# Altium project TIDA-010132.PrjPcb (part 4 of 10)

## Sheet AFE1-RX-TX-INTERFACE.SchDoc
size 431 x 279 mm; Date: Not shown in title block; ApprovedBy: Not shown in title block; CheckedBy: Not shown in title block; Author: Not shown in title block; CompanyName: Not shown in title block; DrawnBy: Avinash N; Engineer: Not shown in title block; Organization: Not shown in title block; Address1: Not shown in title block; Address2: Not shown in title block; Address3: Not shown in title block; Address4: Not shown in title block; DocumentNumber: 1; Revision: Use project parameter SCH_Rev; SheetNumber: 8; SheetTotal: 32; PageSetup: Record=PageOptions¦CenterHorizontal=True¦CenterVertical=True¦PrintScale=1.00¦XCorrection=1.00¦YCorrection=1.00¦PrintKind=0¦BorderSize=5000000¦LeftOffset=0¦BottomOffset=0¦Orientation=2¦PaperLength=1000¦PaperWidth=1000¦Scale=100¦PaperSource=15¦PrintQuality=600¦MediaType=1¦DitherType=10¦PaperKind=Letter¦PrintScaleMode=1
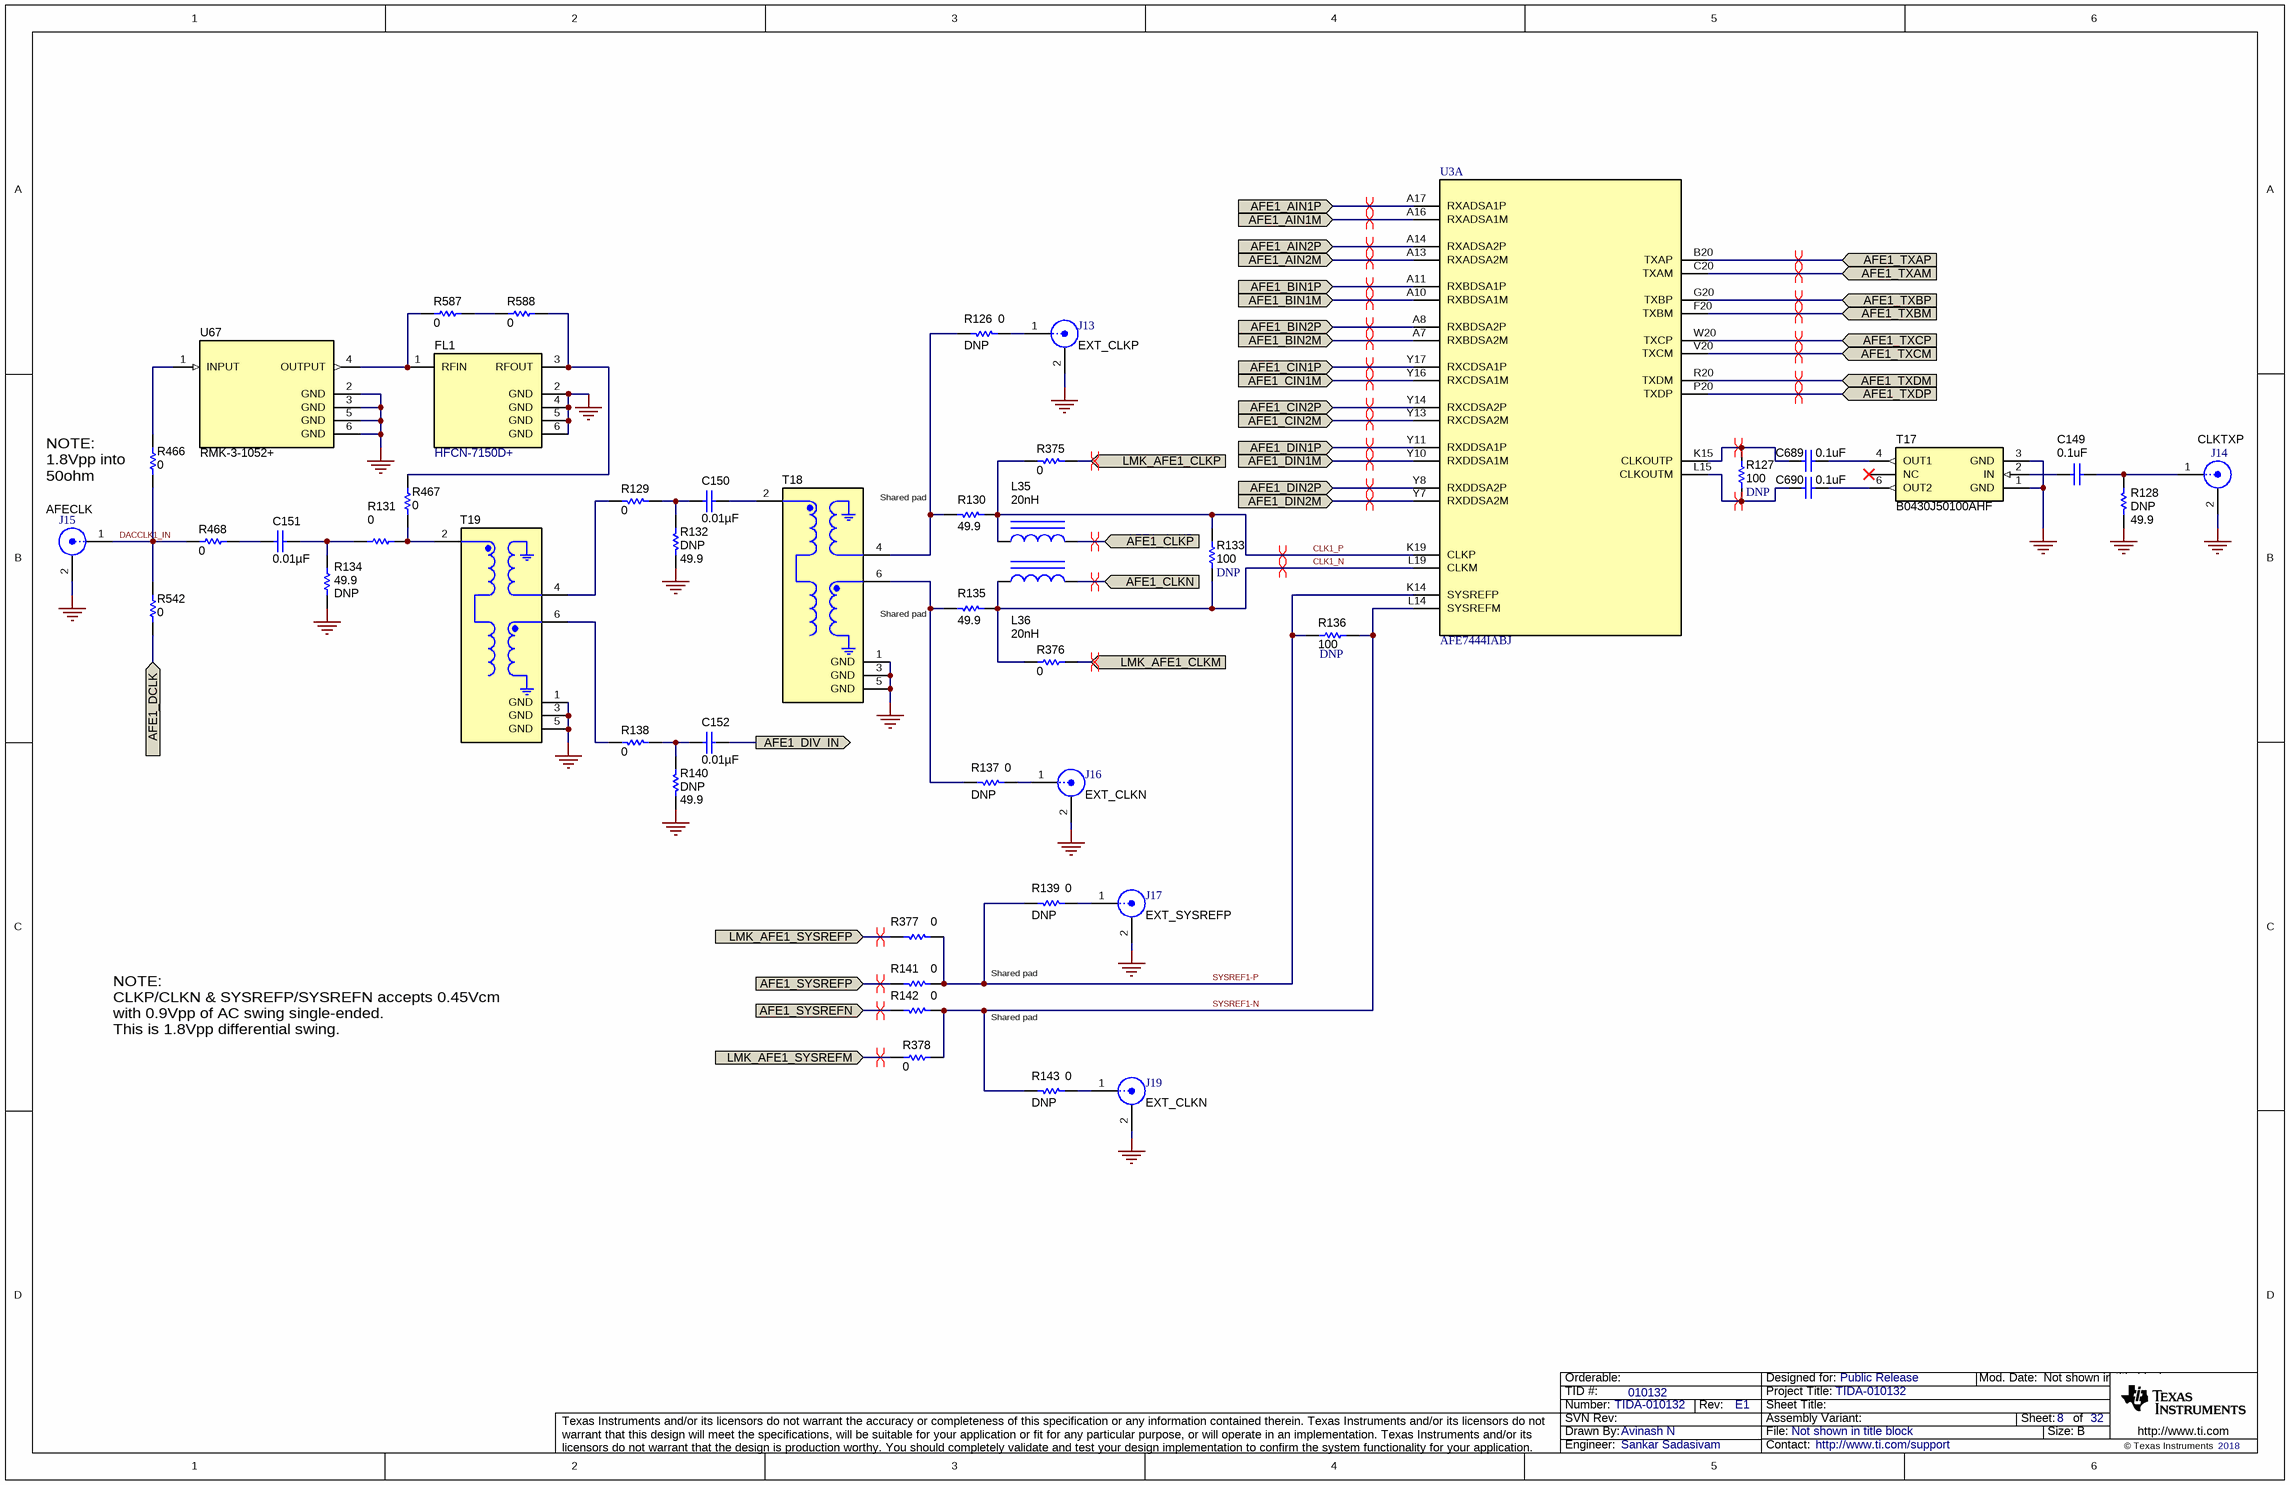
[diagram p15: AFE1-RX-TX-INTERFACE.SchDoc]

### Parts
C149  ValueDisplayed: 0.1uF  [0402_065]  (hidden comment: 550L104KCAT)
C150  ValueDisplayed: 0.01µF  [0402]  (hidden comment: GRM155R71H103KA88D)
C151  ValueDisplayed: 0.01µF  [0402]  (hidden comment: GRM155R71H103KA88D)
C152  ValueDisplayed: 0.01µF  [0402]  (hidden comment: GRM155R71H103KA88D)
C689  ValueDisplayed: 0.1uF  [0402_065]  (hidden comment: 550L104KCAT)
C690  ValueDisplayed: 0.1uF  [0402_065]  (hidden comment: 550L104KCAT)
FL1  HFCN-7150D+  [FV1206-1]
J13  EXT_CLKP  [Molex_0853050232]
J14  CLKTXP  [Molex_0853050232]
J15  AFECLK  [Molex_0853050232]
J16  EXT_CLKN  [Molex_0853050232]
J17  EXT_SYSREFP  [Molex_0853050232]
J19  EXT_CLKN  [Molex_0853050232]
L35  ValueDisplayed: 20nH  [LQG15WZ_02]  (hidden comment: LQG15WZ20NH02D)
L36  ValueDisplayed: 20nH  [LQG15WZ_02]  (hidden comment: LQG15WZ20NH02D)
R126  DNP  ValueDisplayed: 0  [0402]
R127  ValueDisplayed: 100  [0201]  (hidden comment: ERJ-1GEF1000C)
R128  DNP  ValueDisplayed: 49.9  [0402]
R129  ValueDisplayed: 0  [0402]  (hidden comment: ERJ-2GE0R00X)
R130  ValueDisplayed: 49.9  [0402]  (hidden comment: ERJ-2RKF49R9X)
R131  ValueDisplayed: 0  [0402]  (hidden comment: ERJ-2GE0R00X)
R132  DNP  ValueDisplayed: 49.9  [0402]
R133  ValueDisplayed: 100  [0201]  (hidden comment: ERJ-1GEF1000C)
R134  DNP  ValueDisplayed: 49.9  [0402]
R135  ValueDisplayed: 49.9  [0402]  (hidden comment: ERJ-2RKF49R9X)
R136  ValueDisplayed: 100  [0201]  (hidden comment: ERJ-1GEF1000C)
R137  DNP  ValueDisplayed: 0  [0402]
R138  ValueDisplayed: 0  [0402]  (hidden comment: ERJ-2GE0R00X)
R139  DNP  ValueDisplayed: 0  [0402]
R140  DNP  ValueDisplayed: 49.9  [0402]
R141  ValueDisplayed: 0  [0402]  (hidden comment: ERJ-2GE0R00X)
R142  ValueDisplayed: 0  [0402]  (hidden comment: ERJ-2GE0R00X)
R143  DNP  ValueDisplayed: 0  [0402]
R375  ValueDisplayed: 0  [0402]  (hidden comment: ERJ-2GE0R00X)
R376  ValueDisplayed: 0  [0402]  (hidden comment: ERJ-2GE0R00X)
R377  ValueDisplayed: 0  [0402]  (hidden comment: ERJ-2GE0R00X)
R378  ValueDisplayed: 0  [0402]  (hidden comment: ERJ-2GE0R00X)
R466  ValueDisplayed: 0  [0402]  (hidden comment: ERJ-2GE0R00X)
R467  ValueDisplayed: 0  [0402]  (hidden comment: ERJ-2GE0R00X)
R468  ValueDisplayed: 0  [0402]  (hidden comment: ERJ-2GE0R00X)
R542  ValueDisplayed: 0  [0402]  (hidden comment: ERJ-2GE0R00X)
R587  ValueDisplayed: 0  [0402]  (hidden comment: ERJ-2GE0R00X)
R588  ValueDisplayed: 0  [0402]  (hidden comment: ERJ-2GE0R00X)
T17  B0430J50100AHF  [B0430J50100AHF]
T18  NCR2-113+  [MNC_NF1846-1]  (value not drawn)
T19  NCR2-113+  [MNC_NF1846-1]  (value not drawn)
U3  AFE7444IABJ  [ABJ0400A]  (part A of 6)
U67  RMK-3-1052+  [Minicircuits_TT1224]

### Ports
AFE1_AIN1M (in), AFE1_AIN1P (in), AFE1_AIN2M (in), AFE1_AIN2P (in), AFE1_BIN1M (in), AFE1_BIN1P (in), AFE1_BIN2M (in), AFE1_BIN2P (in), AFE1_CIN1M (in), AFE1_CIN1P (in), AFE1_CIN2M (in), AFE1_CIN2P (in), AFE1_CLKN (in), AFE1_CLKP (in), AFE1_DCLK (in), AFE1_DIN1M (in), AFE1_DIN1P (in), AFE1_DIN2M (in), AFE1_DIN2P (in), AFE1_DIV_IN (out), AFE1_SYSREFN (in), AFE1_SYSREFP (in), AFE1_TXAM (in), AFE1_TXAP (in), AFE1_TXBM (in), AFE1_TXBP (in), AFE1_TXCM (in), AFE1_TXCP (in), AFE1_TXDM (in), AFE1_TXDP (in), LMK_AFE1_CLKM (in), LMK_AFE1_CLKP (in), LMK_AFE1_SYSREFM (in), LMK_AFE1_SYSREFP (in)

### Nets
GND: FL1.2(GND) FL1.4(GND) FL1.5(GND) FL1.6(GND) J13.2 J14.2 J15.2 J16.2 J17.2 J19.2 R128.1 R132.1 R134.1 R140.1 T17.1(GND) T17.3(GND) T18.1(GND) T18.3(GND) T18.5(GND) T19.1(GND) T19.3(GND) T19.5(GND) U67.2(GND) U67.3(GND) U67.5(GND) U67.6(GND)
AFE1_AIN1M: U3.A16(RXADSA1M) ; port AFE1_AIN1M
AFE1_AIN1P: U3.A17(RXADSA1P) ; port AFE1_AIN1P
AFE1_AIN2M: U3.A13(RXADSA2M) ; port AFE1_AIN2M
AFE1_AIN2P: U3.A14(RXADSA2P) ; port AFE1_AIN2P
AFE1_BIN1M: U3.A10(RXBDSA1M) ; port AFE1_BIN1M
AFE1_BIN1P: U3.A11(RXBDSA1P) ; port AFE1_BIN1P
AFE1_BIN2M: U3.A7(RXBDSA2M) ; port AFE1_BIN2M
AFE1_BIN2P: U3.A8(RXBDSA2P) ; port AFE1_BIN2P
AFE1_CIN1M: U3.Y16(RXCDSA1M) ; port AFE1_CIN1M
AFE1_CIN1P: U3.Y17(RXCDSA1P) ; port AFE1_CIN1P
AFE1_CIN2M: U3.Y13(RXCDSA2M) ; port AFE1_CIN2M
AFE1_CIN2P: U3.Y14(RXCDSA2P) ; port AFE1_CIN2P
AFE1_CLKN: L36.2 ; port AFE1_CLKN
AFE1_CLKP: L35.2 ; port AFE1_CLKP
AFE1_DCLK: R542.1 ; port AFE1_DCLK
AFE1_DIN1M: U3.Y10(RXDDSA1M) ; port AFE1_DIN1M
AFE1_DIN1P: U3.Y11(RXDDSA1P) ; port AFE1_DIN1P
AFE1_DIN2M: U3.Y7(RXDDSA2M) ; port AFE1_DIN2M
AFE1_DIN2P: U3.Y8(RXDDSA2P) ; port AFE1_DIN2P
AFE1_DIV_IN: C152.1 ; port AFE1_DIV_IN
AFE1_SYSREFN: R142.2 ; port AFE1_SYSREFN
AFE1_SYSREFP: R141.2 ; port AFE1_SYSREFP
AFE1_TXAM: U3.C20(TXAM) ; port AFE1_TXAM
AFE1_TXAP: U3.B20(TXAP) ; port AFE1_TXAP
AFE1_TXBM: U3.F20(TXBM) ; port AFE1_TXBM
AFE1_TXBP: U3.G20(TXBP) ; port AFE1_TXBP
AFE1_TXCM: U3.V20(TXCM) ; port AFE1_TXCM
AFE1_TXCP: U3.W20(TXCP) ; port AFE1_TXCP
AFE1_TXDM: U3.R20(TXDM) ; port AFE1_TXDM
AFE1_TXDP: U3.P20(TXDP) ; port AFE1_TXDP
CLK1_N: L36.1 R133.1 R135.1 R376.2 U3.L19(CLKM)
CLK1_P: L35.1 R130.1 R133.2 R375.2 U3.K19(CLKP)
DACCLK1_IN: J15.1 R466.1 R468.2 R542.2
LMK_AFE1_CLKM: R376.1 ; port LMK_AFE1_CLKM
LMK_AFE1_CLKP: R375.1 ; port LMK_AFE1_CLKP
LMK_AFE1_SYSREFM: R378.2 ; port LMK_AFE1_SYSREFM
LMK_AFE1_SYSREFP: R377.2 ; port LMK_AFE1_SYSREFP
SYSREF1-N: R136.2 R142.1 R143.2 R378.1 U3.L14(SYSREFM)
SYSREF1-P: R136.1 R139.2 R141.1 R377.1 U3.K14(SYSREFP)
NetC149_1: C149.1 J14.1 R128.2
NetC149_2: C149.2 T17.2(IN)
NetC150_1: C150.1 T18.2
NetC150_2: C150.2 R129.1 R132.2
NetC151_1: C151.1 R131.1 R134.2
NetC151_2: C151.2 R468.1
NetC152_2: C152.2 R138.1 R140.2
NetC689_1: C689.1 T17.4(OUT1)
NetC689_2: C689.2 R127.2 U3.K15(CLKOUTP)
NetC690_1: C690.1 T17.6(OUT2)
NetC690_2: C690.2 R127.1 U3.L15(CLKOUTM)
NetFL1_1: FL1.1(RFIN) R587.2 U67.4(OUTPUT)
NetFL1_3: FL1.3(RFOUT) R467.2 R588.1
NetJ13_1: J13.1 R126.1
NetJ16_1: J16.1 R137.1
NetJ17_1: J17.1 R139.1
NetJ19_1: J19.1 R143.1
NetR126_2: R126.2 R130.2 T18.4
NetR129_2: R129.2 T19.4
NetR131_2: R131.2 R467.1 T19.2
NetR135_2: R135.2 R137.2 T18.6
NetR138_2: R138.2 T19.6
NetR466_2: R466.2 U67.1(INPUT)
NetR587_1: R587.1 R588.2

Not connected (* = marked no-connect by the designer): T17 5(NC)*

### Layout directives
differential pair: AFE1_AIN1M, AFE1_AIN1P, AFE1_AIN2M, AFE1_AIN2P, AFE1_BIN1M, AFE1_BIN1P, AFE1_BIN2M, AFE1_BIN2P, AFE1_CIN1M, AFE1_CIN1P, AFE1_CIN2M, AFE1_CIN2P, AFE1_CLKN, AFE1_CLKP, AFE1_DIN1M, AFE1_DIN1P, AFE1_DIN2M, AFE1_DIN2P, AFE1_SYSREFN, AFE1_SYSREFP, AFE1_TXAM, AFE1_TXAP, AFE1_TXBM, AFE1_TXBP, AFE1_TXCM, AFE1_TXCP, AFE1_TXDM, AFE1_TXDP, CLK1_N, CLK1_P, LMK_AFE1_CLKM, LMK_AFE1_CLKP, LMK_AFE1_SYSREFM, LMK_AFE1_SYSREFP, NetC689_2, NetC690_2

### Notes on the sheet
- (near R466) NOTE:
  1.8Vpp into 50ohm
- (near T18) Shared pad
- Shared pad
- NOTE:
  CLKP/CLKN & SYSREFP/SYSREFN accepts 0.45Vcm
  with 0.9Vpp of AC swing single-ended.
  This is 1.8Vpp differential swing.

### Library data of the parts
C149 C689 C690 = CMP-0006211-2: CAP, CERM, 0.1 uF, 16 V, +/- 10%, Unknown, 0402; Manufacturer: AT Ceramics; TaMin_C: -55°C; Polarized: N; SizeAreaWB_mm2: 3; U/M: EA; Value: 0.1uF; TaMax_C: 125°C; SizeZ_mm: 0.65; SizeX_mm: 1; SizeY_mm: 0.5; Cap_Case: 0402; Value2: 16V; Cap_F: 100nF; AEC Category: Q200
C150-C152 = GRM155R71H103KA88D: CAP, CERM, 0.01 µF, 50 V,+/- 10%, X7R, 0402; Manufacturer: MuRata; Polarized: N; CompType: Capacitor; Value: 0.01uF; U/M: EA; Cap_F: 0.00000001; Tolerance_%: 10; Value1: Unknown; VDC_V: 50; Value2: 50V; TaMin_C: -55; TaMax_C: 125; SizeArea_mm2: 0.5; SizeAreaWB_mm2: 3; SizeX_mm: 1; SizeZ_mm: 0.6; AEC Category: Q200; Green_Lifecycle: Active; Green_REACh: Passed
FL1 = CMP-0001869-2: High Pass Filter, 50 Ohm, 79000 to 11000 MHz, FV1206-1; PartNumber: HFCN-3100D+; Manufacturer: Minicircuits; SizeZ_mm: 1.067; SizeX_mm: 3.2; SizeY_mm: 1.6; SizeAreaWB_mm2: 10.92; SizeArea_mm2: 5.12
J13-J17 J19 = CMP-0077224-1: Plug, 50 Ohm, Straight, SMT; PartNumber: 0853050232; Manufacturer: Molex; Cert_UL: Y; ContactFinish: Gold; CT: False; Gender: Male; Voltage_V: 335V
L35 L36 = CMP-0080189-3: Inductor, Multilayer, Air Core, 20 nH, 0.26 A, 1.1 ohm, AEC-Q200 Grade 1, SMD; Manufacturer: MuRata; Irms: 0.26A @ 25C rise; SizeAreaWB_mm2: 3.2; DCR_ohm: 1.1; Value1: 1.1 ohm; Value: 20nH; Imax_A: 2.6dA; SizeZ_mm: 0.6; SizeX_mm: 1; Value2: 0.26A; AEC Qualified: Y; AEC Category: Q200
R126 R129 R131 R137-R139 R141-R143 R375-R378 R466-R468 R542 R587 R588 = ERJ-2GE0R00X: RES, 0, 5%, 0.063 W, 0402; Manufacturer: Panasonic; CompType: Resistor; Value: 0; Value_Code: 0000; Tolerance_%: 5; Power_W: 0.063; Value2: 0.063W; VDC_V: 50; TempCo: 600 ppm/C; SizeArea_mm2: 0.5; SizeX_mm: 1; SizeZ_mm: 0.6; EIA_Code: E24; U/M: EA; AEC Category: Q200; Green_Lifecycle: Active; Green_REACh: Passed
R127 R133 R136 = ERJ-1GEF1000C: RES, 100, 1%, 0.05 W, 0201; Manufacturer: Panasonic; CompType: Resistor; Value: 100; Value_Code: 100R; Tolerance_%: 1; Power_W: 0.05; Value2: 0.05W; VDC_V: 25; TempCo: 200 ppm/C; SizeArea_mm2: 0.18; SizeX_mm: 0.6; SizeY_mm: 0.3; SizeZ_mm: 0.26; EIA_Code: E96; U/M: EA; AEC Category: Q200
R128 R130 R132 R134 R135 R140 = ERJ-2RKF49R9X: RES, 49.9, 1%, 0.1 W, AEC-Q200 Grade 0, 0402; Manufacturer: Panasonic; CompType: Resistor; Value: 49.9; Value_Code: 49R9; Tolerance_%: 1; Power_W: 0.1; Value2: 0.1W; VDC_V: 50; TempCo: 100 ppm/C; SizeArea_mm2: 0.5; SizeZ_mm: 0.6; EIA_Code: E96; U/M: EA; AEC Category: Q200; AEC Qualified: Y; AEC Grade: 0; Green_Lifecycle: Active; Green_REACh: Passed
T17 = CMP-0030061-1: Transformer, Multi-layer balun, SMD; Manufacturer: Anaren; Green_REACh: Incomplete; Green_Lifecycle: Not Set
T18 T19 = NCR2-123+: RF Transformer, 50 Ohm, 3W, SMT; Manufacturer: Minicircuits; SymbolCreator: Altium; SizeAreaWB_mm2: 10.5049; SizeArea_mm2: 5.0049; SizeX_mm: 2.01; SizeY_mm: 2.49; SizeZ_mm: 0.89
U3 = CMP-0084351-1: Quad-Channel RF Sampling Transceiver with 14-bit 9-GSPS DACs and 14-bit 3-GSPS ADCs, ABJ0400A (DSBGA-400); Manufacturer: Texas Instruments; SizeY_mm: 17; AEC Qualified: N; CompType: IC; SizeZ_mm: 2.65; SizeAreaWB_mm2: 361; AEC Category: Q200; SizeArea_mm2: 289
U67 = CMP-0084474-1: Frequency Multiplier, 50Ω, Output 6600 to 10500 MHz, SMD; Manufacturer: Minicircuits; SizeZ_mm: 4.06; SizeAreaWB_mm2: 82.4145; SizeArea_mm2: 49.9745; SizeX_mm: 7.87; SizeY_mm: 6.35

## Sheet AFE1-GROUND.SchDoc
size 431 x 279 mm; Date: Not shown in title block; ApprovedBy: Not shown in title block; CheckedBy: Not shown in title block; Author: Not shown in title block; CompanyName: Not shown in title block; DrawnBy: Avinash N; Engineer: Not shown in title block; Organization: Not shown in title block; Address1: Not shown in title block; Address2: Not shown in title block; Address3: Not shown in title block; Address4: Not shown in title block; DocumentNumber: 1; Revision: Use project parameter SCH_Rev; SheetNumber: 12; SheetTotal: 32; PageSetup: Record=PageOptions¦CenterHorizontal=True¦CenterVertical=True¦PrintScale=1.00¦XCorrection=1.00¦YCorrection=1.00¦PrintKind=0¦BorderSize=5000000¦LeftOffset=0¦BottomOffset=0¦Orientation=2¦PaperLength=1000¦PaperWidth=1000¦Scale=100¦PaperSource=15¦PrintQuality=600¦MediaType=1¦DitherType=10¦PaperKind=Letter¦PrintScaleMode=1
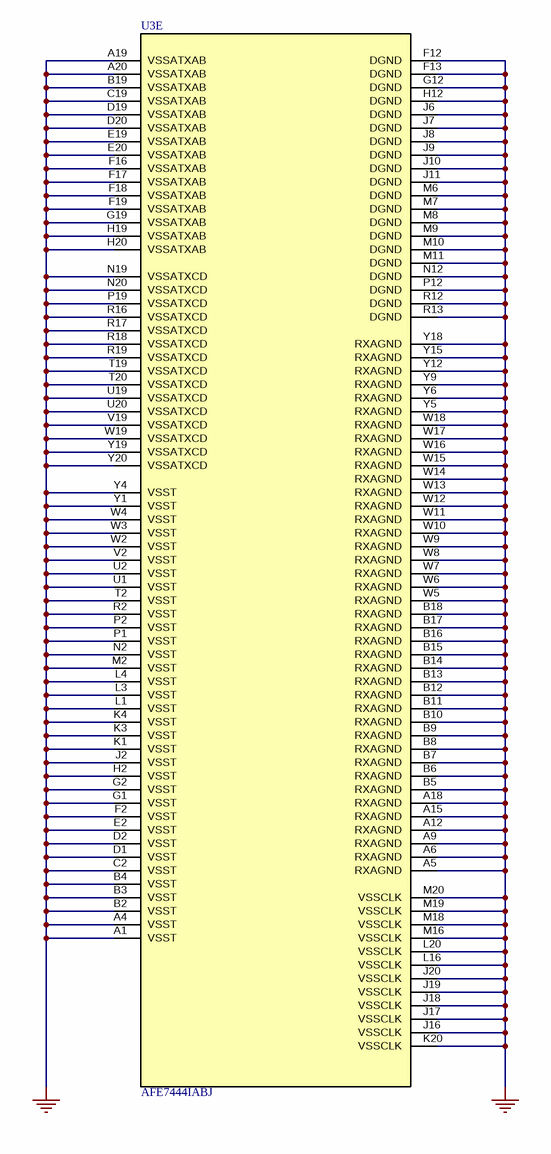
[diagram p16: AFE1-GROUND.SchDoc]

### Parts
U3  AFE7444IABJ  [ABJ0400A]  (part E of 6)

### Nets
GND: U3.A1(VSST) U3.A4(VSST) U3.A5(RXAGND) U3.A6(RXAGND) U3.A9(RXAGND) U3.A12(RXAGND) U3.A15(RXAGND) U3.A18(RXAGND) U3.A19(VSSATXAB) U3.A20(VSSATXAB) U3.B2(VSST) U3.B3(VSST) U3.B4(VSST) U3.B5(RXAGND) U3.B6(RXAGND) U3.B7(RXAGND) U3.B8(RXAGND) U3.B9(RXAGND) U3.B10(RXAGND) U3.B11(RXAGND) U3.B12(RXAGND) U3.B13(RXAGND) U3.B14(RXAGND) U3.B15(RXAGND) U3.B16(RXAGND) U3.B17(RXAGND) U3.B18(RXAGND) U3.B19(VSSATXAB) U3.C2(VSST) U3.C19(VSSATXAB) U3.D1(VSST) U3.D2(VSST) U3.D19(VSSATXAB) U3.D20(VSSATXAB) U3.E2(VSST) U3.E19(VSSATXAB) U3.E20(VSSATXAB) U3.F2(VSST) U3.F12(DGND) U3.F13(DGND) U3.F16(VSSATXAB) U3.F17(VSSATXAB) U3.F18(VSSATXAB) U3.F19(VSSATXAB) U3.G1(VSST) U3.G2(VSST) U3.G12(DGND) U3.G19(VSSATXAB) U3.H2(VSST) U3.H12(DGND) U3.H19(VSSATXAB) U3.H20(VSSATXAB) U3.J2(VSST) U3.J6(DGND) U3.J7(DGND) U3.J8(DGND) U3.J9(DGND) U3.J10(DGND) U3.J11(DGND) U3.J16(VSSCLK) U3.J17(VSSCLK) U3.J18(VSSCLK) U3.J19(VSSCLK) U3.J20(VSSCLK) U3.K1(VSST) U3.K3(VSST) U3.K4(VSST) U3.K20(VSSCLK) U3.L1(VSST) U3.L3(VSST) U3.L4(VSST) U3.L16(VSSCLK) U3.L20(VSSCLK) U3.M2(VSST) U3.M6(DGND) U3.M7(DGND) U3.M8(DGND) U3.M9(DGND) U3.M10(DGND) U3.M11(DGND) U3.M16(VSSCLK) U3.M18(VSSCLK) U3.M19(VSSCLK) U3.M20(VSSCLK) U3.N2(VSST) U3.N12(DGND) U3.N19(VSSATXCD) U3.N20(VSSATXCD) U3.P1(VSST) U3.P2(VSST) U3.P12(DGND) U3.P19(VSSATXCD) U3.R2(VSST) U3.R12(DGND) U3.R13(DGND) U3.R16(VSSATXCD) U3.R17(VSSATXCD) U3.R18(VSSATXCD) U3.R19(VSSATXCD) U3.T2(VSST) U3.T19(VSSATXCD) U3.T20(VSSATXCD) U3.U1(VSST) U3.U2(VSST) U3.U19(VSSATXCD) U3.U20(VSSATXCD) U3.V2(VSST) U3.V19(VSSATXCD) U3.W2(VSST) U3.W3(VSST) U3.W4(VSST) U3.W5(RXAGND) U3.W6(RXAGND) U3.W7(RXAGND) U3.W8(RXAGND) U3.W9(RXAGND) U3.W10(RXAGND) U3.W11(RXAGND) U3.W12(RXAGND) U3.W13(RXAGND) U3.W14(RXAGND) U3.W15(RXAGND) U3.W16(RXAGND) U3.W17(RXAGND) U3.W18(RXAGND) U3.W19(VSSATXCD) U3.Y1(VSST) U3.Y4(VSST) U3.Y5(RXAGND) U3.Y6(RXAGND) U3.Y9(RXAGND) U3.Y12(RXAGND) U3.Y15(RXAGND) U3.Y18(RXAGND) U3.Y19(VSSATXCD) U3.Y20(VSSATXCD)

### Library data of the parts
U3 = CMP-0084351-1: as U3 on sheet AFE1-RX-TX-INTERFACE

## Sheet AFE1-PROGRAMMING INTERFACE.SchDoc
size 431 x 279 mm; Date: Not shown in title block; ApprovedBy: Not shown in title block; CheckedBy: Not shown in title block; Author: Not shown in title block; CompanyName: Not shown in title block; DrawnBy: Avinash N; Engineer: Not shown in title block; Organization: Not shown in title block; Address1: Not shown in title block; Address2: Not shown in title block; Address3: Not shown in title block; Address4: Not shown in title block; DocumentNumber: 1; Revision: Use project parameter SCH_Rev; SheetNumber: 10; SheetTotal: 32; PageSetup: Record=PageOptions¦CenterHorizontal=True¦CenterVertical=True¦PrintScale=1.00¦XCorrection=1.00¦YCorrection=1.00¦PrintKind=0¦BorderSize=5000000¦LeftOffset=0¦BottomOffset=0¦Orientation=2¦PaperLength=1000¦PaperWidth=1000¦Scale=100¦PaperSource=15¦PrintQuality=600¦MediaType=1¦DitherType=10¦PaperKind=Letter¦PrintScaleMode=1
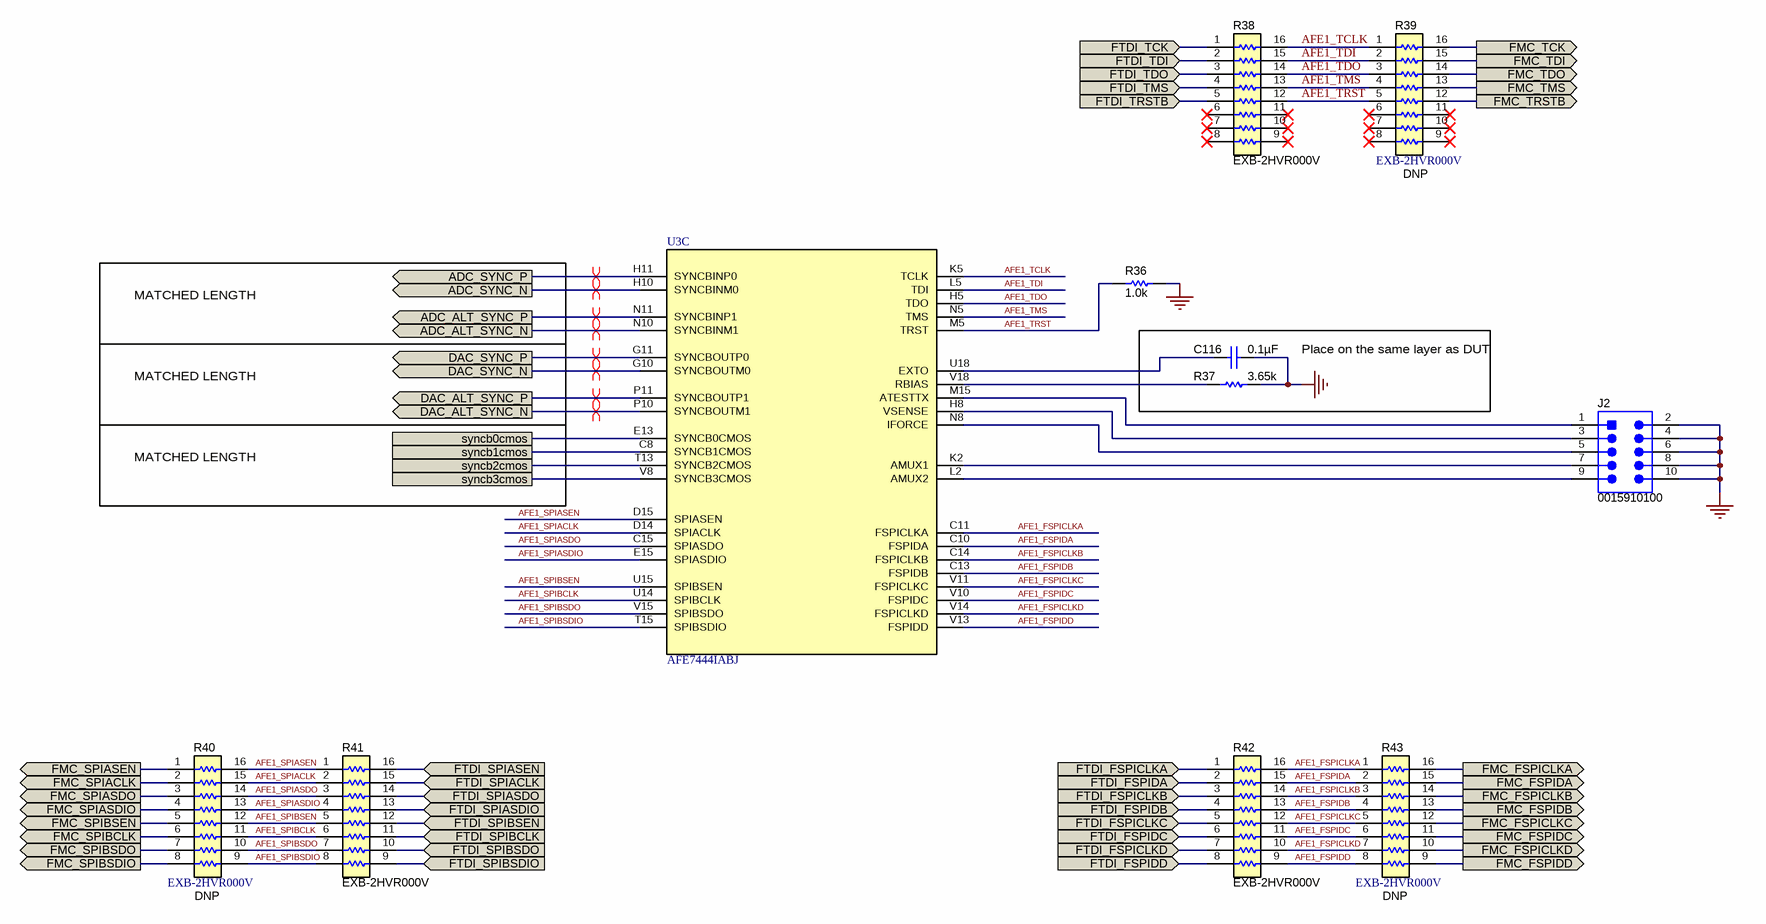
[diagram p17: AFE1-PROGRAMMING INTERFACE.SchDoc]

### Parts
C116  ValueDisplayed: 0.1µF  [0201]  (hidden comment: GRM033C71A104KE14D)
J2  0015910100  [Molex_0015910100]
R36  ValueDisplayed: 1.0k  [0402]  (hidden comment: CRCW04021K00JNED)
R37  ValueDisplayed: 3.65k  [0402]  (hidden comment: ERJ-2RKF3651X)
R38  EXB-2HVR000V  [RESCAXS_EXB-2HV]
R39  DNP  PartNumber: EXB-2HVR000V  [RESCAXS_EXB-2HV]
R40  DNP  PartNumber: EXB-2HVR000V  [RESCAXS_EXB-2HV]
R41  EXB-2HVR000V  [RESCAXS_EXB-2HV]
R42  EXB-2HVR000V  [RESCAXS_EXB-2HV]
R43  DNP  PartNumber: EXB-2HVR000V  [RESCAXS_EXB-2HV]
U3  AFE7444IABJ  [ABJ0400A]  (part C of 6)

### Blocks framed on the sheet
Place on the same layer as DUT: C116 R37

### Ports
ADC_ALT_SYNC_N (out), ADC_ALT_SYNC_P (out), ADC_SYNC_N (out), ADC_SYNC_P (out), DAC_ALT_SYNC_N (out), DAC_ALT_SYNC_P (out), DAC_SYNC_N (out), DAC_SYNC_P (out), FMC_FSPICLKA (out), FMC_FSPICLKB (out), FMC_FSPICLKC (out), FMC_FSPICLKD (out), FMC_FSPIDA (out), FMC_FSPIDB (out), FMC_FSPIDC (out), FMC_FSPIDD (out), FMC_SPIACLK (out), FMC_SPIASDIO (out), FMC_SPIASDO (out), FMC_SPIASEN (out), FMC_SPIBCLK (out), FMC_SPIBSDIO (out), FMC_SPIBSDO (out), FMC_SPIBSEN (out), FMC_TCK (out), FMC_TDI (out), FMC_TDO (out), FMC_TMS (out), FMC_TRSTB (out), FTDI_FSPICLKA (in), FTDI_FSPICLKB (in), FTDI_FSPICLKC (in), FTDI_FSPICLKD (in), FTDI_FSPIDA (in), FTDI_FSPIDB (in), FTDI_FSPIDC (in), FTDI_FSPIDD (in), FTDI_SPIACLK (in), FTDI_SPIASDIO (in), FTDI_SPIASDO (in), FTDI_SPIASEN (in), FTDI_SPIBCLK (in), FTDI_SPIBSDIO (in), FTDI_SPIBSDO (in), FTDI_SPIBSEN (in), FTDI_TCK (in), FTDI_TDI (in), FTDI_TDO (in), FTDI_TMS (in), FTDI_TRSTB (in), syncb0cmos, syncb1cmos, syncb2cmos, syncb3cmos

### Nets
GND: C116.1 J2.2 J2.4 J2.6 J2.8 J2.10 R36.1 R37.2
ADC_ALT_SYNC_N: U3.N10(SYNCBINM1) ; port ADC_ALT_SYNC_N
ADC_ALT_SYNC_P: U3.N11(SYNCBINP1) ; port ADC_ALT_SYNC_P
ADC_SYNC_N: U3.H10(SYNCBINM0) ; port ADC_SYNC_N
ADC_SYNC_P: U3.H11(SYNCBINP0) ; port ADC_SYNC_P
AFE1_FSPICLKA: R42.16 R43.1 U3.C11(FSPICLKA)
AFE1_FSPICLKB: R42.14 R43.3 U3.C14(FSPICLKB)
AFE1_FSPICLKC: R42.12 R43.5 U3.V11(FSPICLKC)
AFE1_FSPICLKD: R42.10 R43.7 U3.V14(FSPICLKD)
AFE1_FSPIDA: R42.15 R43.2 U3.C10(FSPIDA)
AFE1_FSPIDB: R42.13 R43.4 U3.C13(FSPIDB)
AFE1_FSPIDC: R42.11 R43.6 U3.V10(FSPIDC)
AFE1_FSPIDD: R42.9 R43.8 U3.V13(FSPIDD)
AFE1_SPIACLK: R40.15 R41.2 U3.D14(SPIACLK)
AFE1_SPIASDIO: R40.13 R41.4 U3.E15(SPIASDIO)
AFE1_SPIASDO: R40.14 R41.3 U3.C15(SPIASDO)
AFE1_SPIASEN: R40.16 R41.1 U3.D15(SPIASEN)
AFE1_SPIBCLK: R40.11 R41.6 U3.U14(SPIBCLK)
AFE1_SPIBSDIO: R40.9 R41.8 U3.T15(SPIBSDIO)
AFE1_SPIBSDO: R40.10 R41.7 U3.V15(SPIBSDO)
AFE1_SPIBSEN: R40.12 R41.5 U3.U15(SPIBSEN)
AFE1_TCLK: R38.16 R39.1 U3.K5(TCLK)
AFE1_TDI: R38.15 R39.2 U3.L5(TDI)
AFE1_TDO: R38.14 R39.3 U3.H5(TDO)
AFE1_TMS: R38.13 R39.4 U3.N5(TMS)
AFE1_TRST: R36.2 R38.12 R39.5 U3.M5(TRST)
DAC_ALT_SYNC_N: U3.P10(SYNCBOUTM1) ; port DAC_ALT_SYNC_N
DAC_ALT_SYNC_P: U3.P11(SYNCBOUTP1) ; port DAC_ALT_SYNC_P
DAC_SYNC_N: U3.G10(SYNCBOUTM0) ; port DAC_SYNC_N
DAC_SYNC_P: U3.G11(SYNCBOUTP0) ; port DAC_SYNC_P
FMC_FSPICLKA: R43.16 ; port FMC_FSPICLKA
FMC_FSPICLKB: R43.14 ; port FMC_FSPICLKB
FMC_FSPICLKC: R43.12 ; port FMC_FSPICLKC
FMC_FSPICLKD: R43.10 ; port FMC_FSPICLKD
FMC_FSPIDA: R43.15 ; port FMC_FSPIDA
FMC_FSPIDB: R43.13 ; port FMC_FSPIDB
FMC_FSPIDC: R43.11 ; port FMC_FSPIDC
FMC_FSPIDD: R43.9 ; port FMC_FSPIDD
FMC_SPIACLK: R40.2 ; port FMC_SPIACLK
FMC_SPIASDIO: R40.4 ; port FMC_SPIASDIO
FMC_SPIASDO: R40.3 ; port FMC_SPIASDO
FMC_SPIASEN: R40.1 ; port FMC_SPIASEN
FMC_SPIBCLK: R40.6 ; port FMC_SPIBCLK
FMC_SPIBSDIO: R40.8 ; port FMC_SPIBSDIO
FMC_SPIBSDO: R40.7 ; port FMC_SPIBSDO
FMC_SPIBSEN: R40.5 ; port FMC_SPIBSEN
FMC_TCK: R39.16 ; port FMC_TCK
FMC_TDI: R39.15 ; port FMC_TDI
FMC_TDO: R39.14 ; port FMC_TDO
FMC_TMS: R39.13 ; port FMC_TMS
FMC_TRSTB: R39.12 ; port FMC_TRSTB
FTDI_FSPICLKA: R42.1 ; port FTDI_FSPICLKA
FTDI_FSPICLKB: R42.3 ; port FTDI_FSPICLKB
FTDI_FSPICLKC: R42.5 ; port FTDI_FSPICLKC
FTDI_FSPICLKD: R42.7 ; port FTDI_FSPICLKD
FTDI_FSPIDA: R42.2 ; port FTDI_FSPIDA
FTDI_FSPIDB: R42.4 ; port FTDI_FSPIDB
FTDI_FSPIDC: R42.6 ; port FTDI_FSPIDC
FTDI_FSPIDD: R42.8 ; port FTDI_FSPIDD
FTDI_SPIACLK: R41.15 ; port FTDI_SPIACLK
FTDI_SPIASDIO: R41.13 ; port FTDI_SPIASDIO
FTDI_SPIASDO: R41.14 ; port FTDI_SPIASDO
FTDI_SPIASEN: R41.16 ; port FTDI_SPIASEN
FTDI_SPIBCLK: R41.11 ; port FTDI_SPIBCLK
FTDI_SPIBSDIO: R41.9 ; port FTDI_SPIBSDIO
FTDI_SPIBSDO: R41.10 ; port FTDI_SPIBSDO
FTDI_SPIBSEN: R41.12 ; port FTDI_SPIBSEN
FTDI_TCK: R38.1 ; port FTDI_TCK
FTDI_TDI: R38.2 ; port FTDI_TDI
FTDI_TDO: R38.3 ; port FTDI_TDO
FTDI_TMS: R38.4 ; port FTDI_TMS
FTDI_TRSTB: R38.5 ; port FTDI_TRSTB
syncb0cmos: U3.E13(SYNCB0CMOS) ; port syncb0cmos
syncb1cmos: U3.C8(SYNCB1CMOS) ; port syncb1cmos
syncb2cmos: U3.T13(SYNCB2CMOS) ; port syncb2cmos
syncb3cmos: U3.V8(SYNCB3CMOS) ; port syncb3cmos
NetC116_2: C116.2 U3.U18(EXTO)
NetJ2_1: J2.1 U3.M15(ATESTTX)
NetJ2_3: J2.3 U3.H8(VSENSE)
NetJ2_5: J2.5 U3.N8(IFORCE)
NetJ2_7: J2.7 U3.K2(AMUX1)
NetJ2_9: J2.9 U3.L2(AMUX2)
NetR37_1: R37.1 U3.V18(RBIAS)

Not connected (* = marked no-connect by the designer): R38 6* 7* 8* 9* 10* 11*; R39 6* 7* 8* 9* 10* 11*

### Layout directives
differential pair: ADC_ALT_SYNC_N, ADC_ALT_SYNC_P, ADC_SYNC_N, ADC_SYNC_P, DAC_ALT_SYNC_N, DAC_ALT_SYNC_P, DAC_SYNC_N, DAC_SYNC_P

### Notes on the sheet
- MATCHED LENGTH

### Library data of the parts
C116 = GRM033C71A104KE14D: CAP, CERM, 0.1 µF, 10 V,+/- 10%, X7S, 0201; Manufacturer: MuRata; Polarized: N; CompType: Capacitor; Value: 0.1uF; U/M: EA; Cap_F: 0.0000001; Tolerance_%: 10; Value1: Unknown; Value2: 10V; TaMin_C: -55; TaMax_C: 125; SizeArea_mm2: 0.18; SizeAreaWB_mm2: 2.08; SizeX_mm: 0.6; SizeY_mm: 0.3; SizeZ_mm: 0.26; AEC Category: Q200
J2 = 0015910100: Header, 100mil, 5x2, SMT; Manufacturer: Molex; SymbolCreator: a0412235; Green_Lifecycle: Active; Green_REACh: Passed
R36 = CRCW04021K00JNED: RES, 1.0 k, 5%, 0.063 W, 0402; Manufacturer: Vishay-Dale; CompType: Resistor; Value: 1.0k; Res_ohm: 1000; Value_Code: 1k00; Tolerance_%: 5; Power_W: 0.063; Value2: 0.063W; VDC_V: 50; TempCo: 200 ppm/C; SizeArea_mm2: 0.5; SizeX_mm: 1; SizeZ_mm: 0.6; EIA_Code: E24; U/M: EA; AEC Category: Q200; Green_Lifecycle: Active; Green_REACh: Passed
R37 = ERJ-2RKF3651X: RES, 3.65 k, 1%, 0.1 W, AEC-Q200 Grade 0, 0402; Manufacturer: Panasonic; CompType: Resistor; Value: 3.65k; Res_ohm: 3650; Value_Code: 3k65; Tolerance_%: 1; Power_W: 0.1; Value2: 0.1W; VDC_V: 50; TempCo: 100 ppm/C; SizeArea_mm2: 0.5; SizeZ_mm: 0.6; EIA_Code: E96; U/M: EA; AEC Category: Q200; AEC Qualified: Y; AEC Grade: 0
R38-R43 = CMP-0015352-2: RES, 0, 5%, 0.0625 W, Resistor Array - 8x1; Manufacturer: Panasonic; Power_W: 62.5mW; TempCo: ppm/C; Value_Code: 0000; U/M: EA; Value: 0; EIA_Code: E24; AEC Category: Q200
U3 = CMP-0084351-1: as U3 on sheet AFE1-RX-TX-INTERFACE

## Sheet AFE1-GPIOs.SchDoc
size 431 x 279 mm; Date: Not shown in title block; ApprovedBy: Not shown in title block; CheckedBy: Not shown in title block; Author: Not shown in title block; CompanyName: Not shown in title block; DrawnBy: Avinash N; Engineer: Not shown in title block; Organization: Not shown in title block; Address1: Not shown in title block; Address2: Not shown in title block; Address3: Not shown in title block; Address4: Not shown in title block; DocumentNumber: 1; Revision: Use project parameter SCH_Rev; SheetNumber: 11; SheetTotal: 32; PageSetup: Record=PageOptions¦CenterHorizontal=True¦CenterVertical=True¦PrintScale=1.00¦XCorrection=1.00¦YCorrection=1.00¦PrintKind=0¦BorderSize=5000000¦LeftOffset=0¦BottomOffset=0¦Orientation=2¦PaperLength=1000¦PaperWidth=1000¦Scale=100¦PaperSource=15¦PrintQuality=600¦MediaType=1¦DitherType=10¦PaperKind=Letter¦PrintScaleMode=1
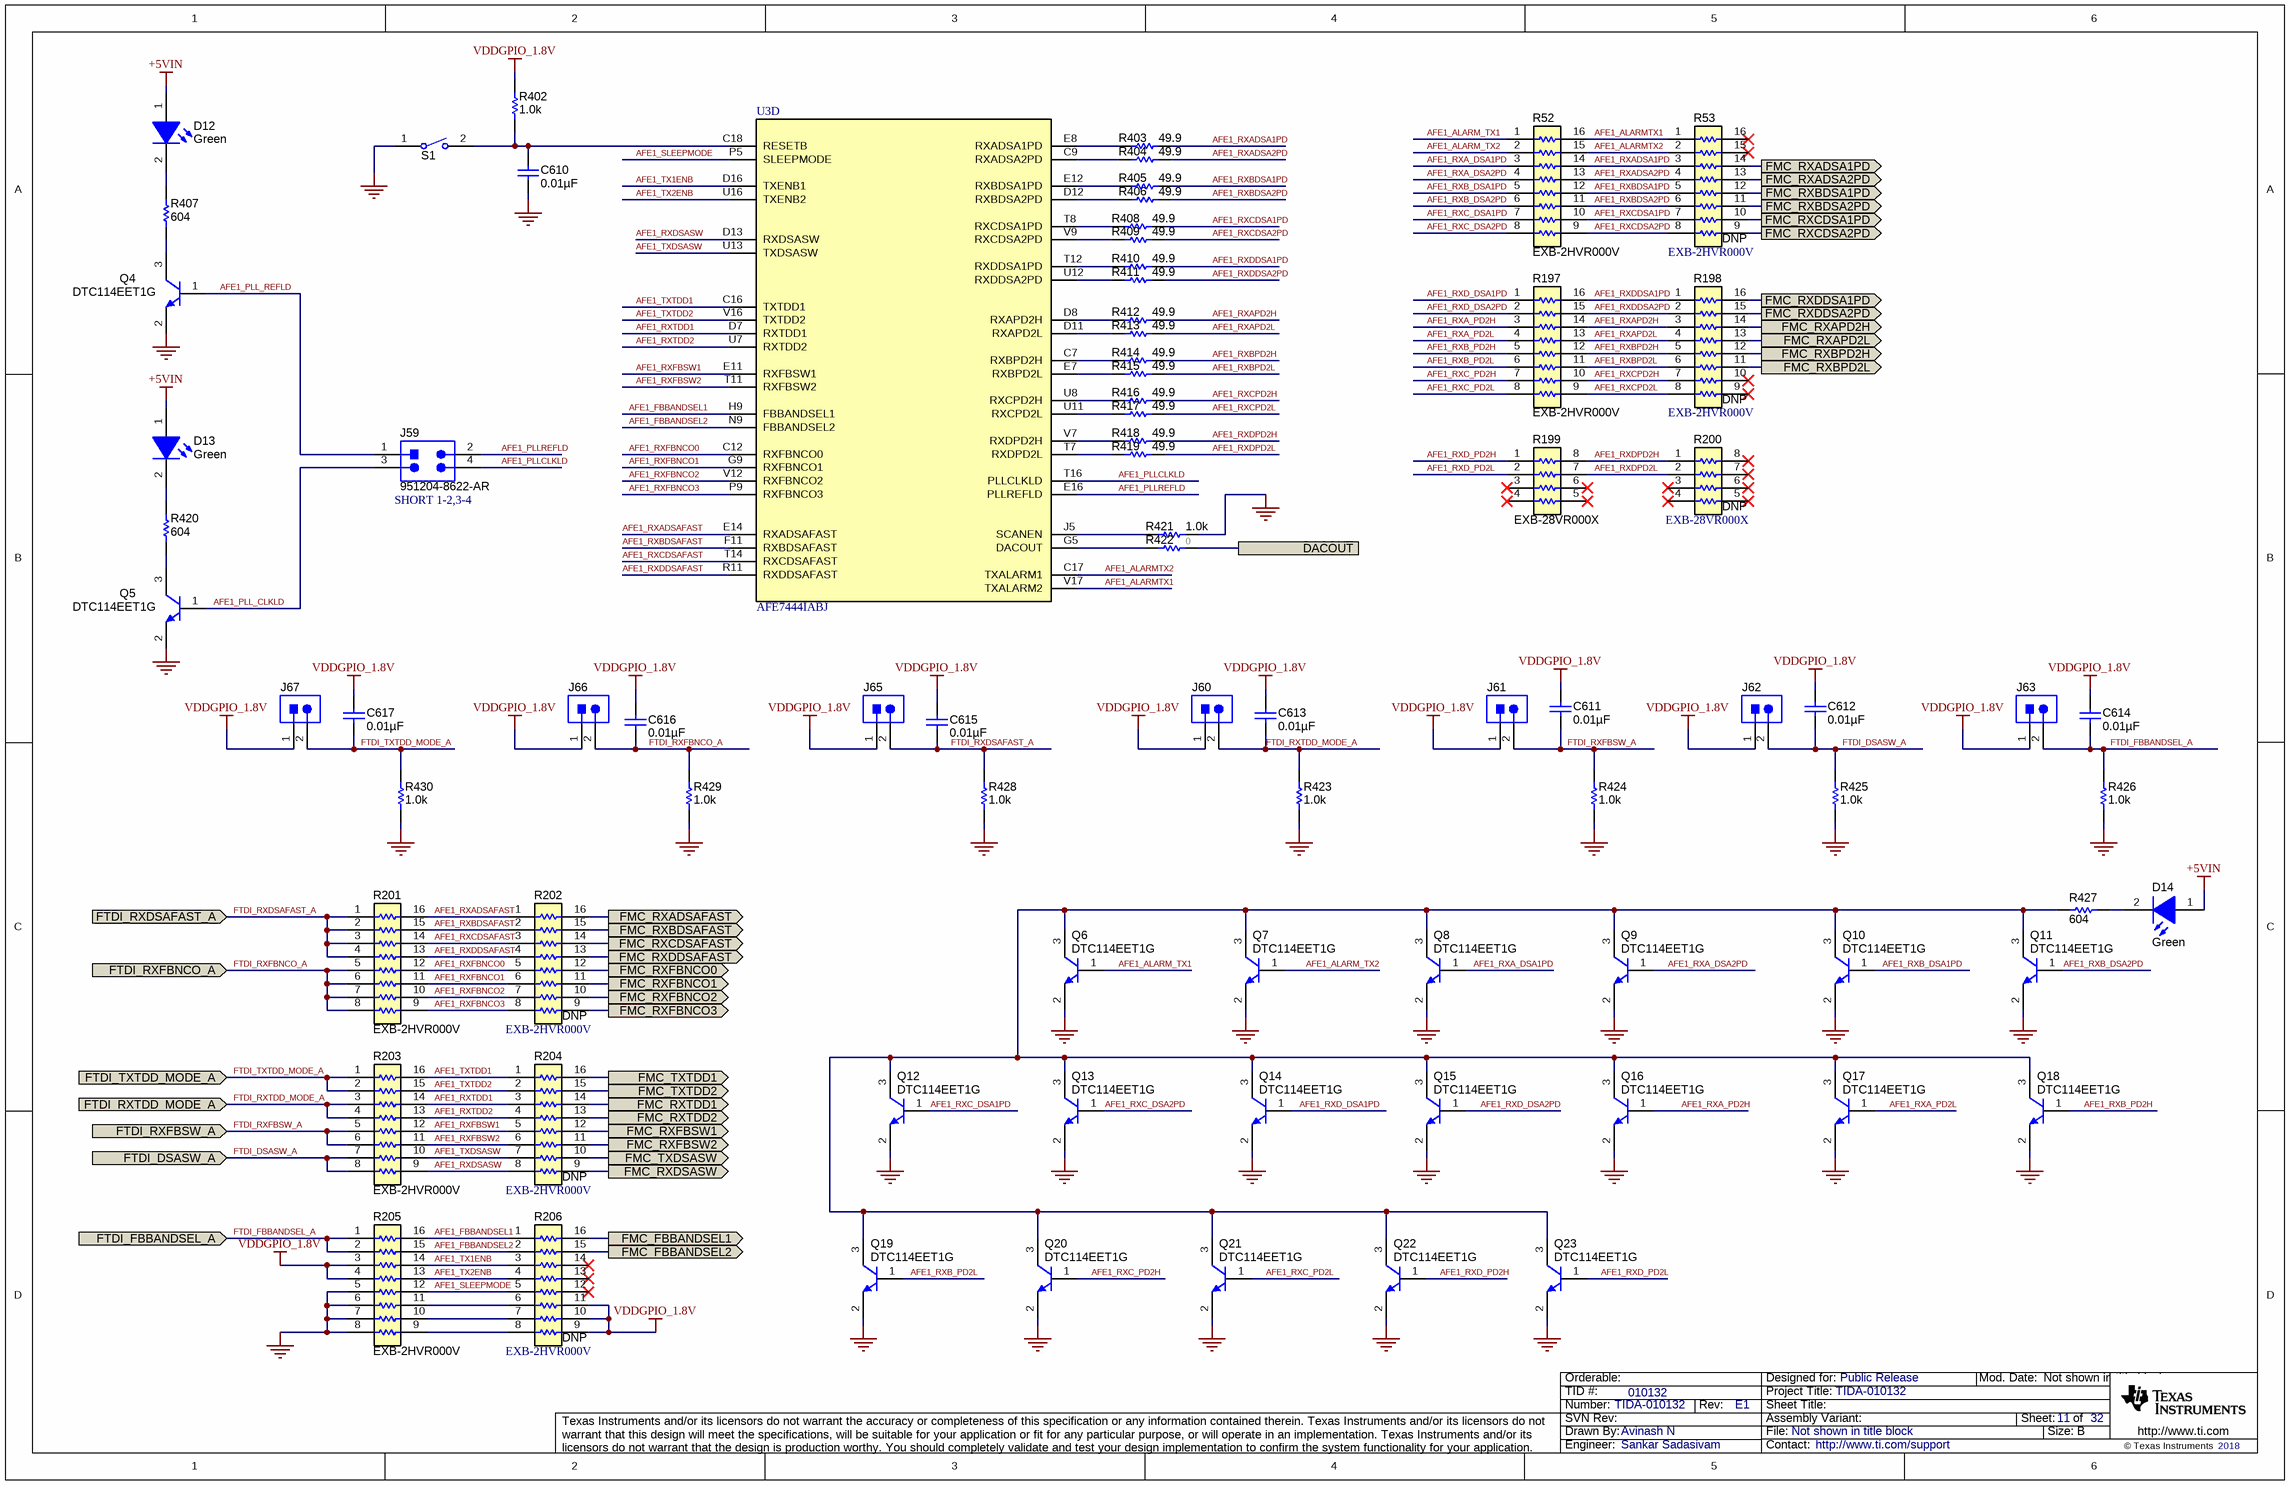
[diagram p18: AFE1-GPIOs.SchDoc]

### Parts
C610  ValueDisplayed: 0.01µF  [0402]  (hidden comment: 0402ZC103KAT2A)
C611  ValueDisplayed: 0.01µF  [0402]  (hidden comment: 0402ZC103KAT2A)
C612  ValueDisplayed: 0.01µF  [0402]  (hidden comment: 0402ZC103KAT2A)
C613  ValueDisplayed: 0.01µF  [0402]  (hidden comment: 0402ZC103KAT2A)
C614  ValueDisplayed: 0.01µF  [0402]  (hidden comment: 0402ZC103KAT2A)
C615  ValueDisplayed: 0.01µF  [0402]  (hidden comment: 0402ZC103KAT2A)
C616  ValueDisplayed: 0.01µF  [0402]  (hidden comment: 0402ZC103KAT2A)
C617  ValueDisplayed: 0.01µF  [0402]  (hidden comment: 0402ZC103KAT2A)
D12  value Green  [LTST-C191_Green]  (hidden comment: LTST-C191TGKT)
D13  value Green  [LTST-C191_Green]  (hidden comment: LTST-C191TGKT)
D14  value Green  [LTST-C191_Green]  (hidden comment: LTST-C191TGKT)
J59  951204-8622-AR  [3M_951204-8622]
J60  TSW-102-07-T-S  [Samtec_TSW-102-07-T-S]  (value not drawn)
J61  TSW-102-07-T-S  [Samtec_TSW-102-07-T-S]  (value not drawn)
J62  TSW-102-07-T-S  [Samtec_TSW-102-07-T-S]  (value not drawn)
J63  TSW-102-07-T-S  [Samtec_TSW-102-07-T-S]  (value not drawn)
J65  TSW-102-07-T-S  [Samtec_TSW-102-07-T-S]  (value not drawn)
J66  TSW-102-07-T-S  [Samtec_TSW-102-07-T-S]  (value not drawn)
J67  TSW-102-07-T-S  [Samtec_TSW-102-07-T-S]  (value not drawn)
Q4  DTC114EET1G  [SOT-416]
Q5  DTC114EET1G  [SOT-416]
Q6  DTC114EET1G  [SOT-416]
Q7  DTC114EET1G  [SOT-416]
Q8  DTC114EET1G  [SOT-416]
Q9  DTC114EET1G  [SOT-416]
Q10  DTC114EET1G  [SOT-416]
Q11  DTC114EET1G  [SOT-416]
Q12  DTC114EET1G  [SOT-416]
Q13  DTC114EET1G  [SOT-416]
Q14  DTC114EET1G  [SOT-416]
Q15  DTC114EET1G  [SOT-416]
Q16  DTC114EET1G  [SOT-416]
Q17  DTC114EET1G  [SOT-416]
Q18  DTC114EET1G  [SOT-416]
Q19  DTC114EET1G  [SOT-416]
Q20  DTC114EET1G  [SOT-416]
Q21  DTC114EET1G  [SOT-416]
Q22  DTC114EET1G  [SOT-416]
Q23  DTC114EET1G  [SOT-416]
R52  EXB-2HVR000V  [RESCAXS_EXB-2HV]
R53  DNP  PartNumber: EXB-2HVR000V  [RESCAXS_EXB-2HV]
R197  EXB-2HVR000V  [RESCAXS_EXB-2HV]
R198  DNP  PartNumber: EXB-2HVR000V  [RESCAXS_EXB-2HV]
R199  EXB-28VR000X  [0804-8]
R200  DNP  PartNumber: EXB-28VR000X  [0804-8]
R201  EXB-2HVR000V  [RESCAXS_EXB-2HV]
R202  DNP  PartNumber: EXB-2HVR000V  [RESCAXS_EXB-2HV]
R203  EXB-2HVR000V  [RESCAXS_EXB-2HV]
R204  DNP  PartNumber: EXB-2HVR000V  [RESCAXS_EXB-2HV]
R205  EXB-2HVR000V  [RESCAXS_EXB-2HV]
R206  DNP  PartNumber: EXB-2HVR000V  [RESCAXS_EXB-2HV]
R402  ValueDisplayed: 1.0k  [0402]  (hidden comment: CRCW04021K00JNED)
R403  ValueDisplayed: 49.9  [0402]  (hidden comment: ERJ-2RKF49R9X)
R404  ValueDisplayed: 49.9  [0402]  (hidden comment: ERJ-2RKF49R9X)
R405  ValueDisplayed: 49.9  [0402]  (hidden comment: ERJ-2RKF49R9X)
R406  ValueDisplayed: 49.9  [0402]  (hidden comment: ERJ-2RKF49R9X)
R407  ValueDisplayed: 604  [0402]  (hidden comment: CRCW0402604RFKED)
R408  ValueDisplayed: 49.9  [0402]  (hidden comment: ERJ-2RKF49R9X)
R409  ValueDisplayed: 49.9  [0402]  (hidden comment: ERJ-2RKF49R9X)
R410  ValueDisplayed: 49.9  [0402]  (hidden comment: ERJ-2RKF49R9X)
R411  ValueDisplayed: 49.9  [0402]  (hidden comment: ERJ-2RKF49R9X)
R412  ValueDisplayed: 49.9  [0402]  (hidden comment: ERJ-2RKF49R9X)
R413  ValueDisplayed: 49.9  [0402]  (hidden comment: ERJ-2RKF49R9X)
R414  ValueDisplayed: 49.9  [0402]  (hidden comment: ERJ-2RKF49R9X)
R415  ValueDisplayed: 49.9  [0402]  (hidden comment: ERJ-2RKF49R9X)
R416  ValueDisplayed: 49.9  [0402]  (hidden comment: ERJ-2RKF49R9X)
R417  ValueDisplayed: 49.9  [0402]  (hidden comment: ERJ-2RKF49R9X)
R418  ValueDisplayed: 49.9  [0402]  (hidden comment: ERJ-2RKF49R9X)
R419  ValueDisplayed: 49.9  [0402]  (hidden comment: ERJ-2RKF49R9X)
R420  ValueDisplayed: 604  [0402]  (hidden comment: CRCW0402604RFKED)
R421  ValueDisplayed: 1.0k  [0402]  (hidden comment: CRCW04021K00JNED)
R422  ValueDisplayed: 0  [0603]  (hidden comment: CRCW06030000Z0EA)
R423  ValueDisplayed: 1.0k  [0402]  (hidden comment: CRCW04021K00JNED)
R424  ValueDisplayed: 1.0k  [0402]  (hidden comment: CRCW04021K00JNED)
R425  ValueDisplayed: 1.0k  [0402]  (hidden comment: CRCW04021K00JNED)
R426  ValueDisplayed: 1.0k  [0402]  (hidden comment: CRCW04021K00JNED)
R427  ValueDisplayed: 604  [0402]  (hidden comment: CRCW0402604RFKED)
R428  ValueDisplayed: 1.0k  [0402]  (hidden comment: CRCW04021K00JNED)
R429  ValueDisplayed: 1.0k  [0402]  (hidden comment: CRCW04021K00JNED)
R430  ValueDisplayed: 1.0k  [0402]  (hidden comment: CRCW04021K00JNED)
S1  147873-2  [SW_147873-2]  (value not drawn)
U3  AFE7444IABJ  [ABJ0400A]  (part D of 6)

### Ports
DACOUT, FMC_FBBANDSEL1 (out), FMC_FBBANDSEL2 (out), FMC_RXADSA1PD (out), FMC_RXADSA2PD (out), FMC_RXADSAFAST (out), FMC_RXAPD2H (out), FMC_RXAPD2L (out), FMC_RXBDSA1PD (out), FMC_RXBDSA2PD (out), FMC_RXBDSAFAST (out), FMC_RXBPD2H (out), FMC_RXBPD2L (out), FMC_RXCDSA1PD (out), FMC_RXCDSA2PD (out), FMC_RXCDSAFAST (out), FMC_RXDDSA1PD (out), FMC_RXDDSA2PD (out), FMC_RXDDSAFAST (out), FMC_RXDSASW (out), FMC_RXFBNCO0 (out), FMC_RXFBNCO1 (out), FMC_RXFBNCO2 (out), FMC_RXFBNCO3 (out), FMC_RXFBSW1 (out), FMC_RXFBSW2 (out), FMC_RXTDD1 (out), FMC_RXTDD2 (out), FMC_TXDSASW (out), FMC_TXTDD1 (out), FMC_TXTDD2 (out), FTDI_DSASW_A (in), FTDI_FBBANDSEL_A (in), FTDI_RXDSAFAST_A (in), FTDI_RXFBNCO_A (in), FTDI_RXFBSW_A (in), FTDI_RXTDD_MODE_A (in), FTDI_TXTDD_MODE_A (in)

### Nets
+5VIN: D12.1(A) D13.1(A) D14.1(A)
GND: C610.2 Q4.2(E) Q5.2(E) Q6.2(E) Q7.2(E) Q8.2(E) Q9.2(E) Q10.2(E) Q11.2(E) Q12.2(E) Q13.2(E) Q14.2(E) Q15.2(E) Q16.2(E) Q17.2(E) Q18.2(E) Q19.2(E) Q20.2(E) Q21.2(E) Q22.2(E) Q23.2(E) R205.5 R205.6 R205.7 R205.8 R421.2 R423.1 R424.1 R425.1 R426.1 R428.1 R429.1 R430.1 S1.1
VDDGPIO_1.8V: C611.1 C612.1 C613.1 C614.1 C615.1 C616.1 C617.1 J60.1 J61.1 J62.1 J63.1 J65.1 J66.1 J67.1 R205.3 R205.4 R206.9 R206.10 R206.11 R402.2
AFE1_ALARM_TX1: Q6.1(B) R52.1
AFE1_ALARM_TX2: Q7.1(B) R52.2
AFE1_ALARMTX1: R52.16 R53.1 U3.V17(TXALARM2)
AFE1_ALARMTX2: R52.15 R53.2 U3.C17(TXALARM1)
AFE1_FBBANDSEL1: R205.16 R206.1 U3.H9(FBBANDSEL1)
AFE1_FBBANDSEL2: R205.15 R206.2 U3.N9(FBBANDSEL2)
AFE1_PLL_CLKLD: J59.3 Q5.1(B)
AFE1_PLL_REFLD: J59.1 Q4.1(B)
AFE1_PLLCLKLD: J59.4 U3.T16(PLLCLKLD)
AFE1_PLLREFLD: J59.2 U3.E16(PLLREFLD)
AFE1_RXA_DSA1PD: Q8.1(B) R52.3
AFE1_RXA_DSA2PD: Q9.1(B) R52.4
AFE1_RXA_PD2H: Q16.1(B) R197.3
AFE1_RXA_PD2L: Q17.1(B) R197.4
AFE1_RXADSA1PD: R52.14 R53.3 R403.2
AFE1_RXADSA2PD: R52.13 R53.4 R404.2
AFE1_RXADSAFAST: R201.16 R202.1 U3.E14(RXADSAFAST)
AFE1_RXAPD2H: R197.14 R198.3 R412.2
AFE1_RXAPD2L: R197.13 R198.4 R413.2
AFE1_RXB_DSA1PD: Q10.1(B) R52.5
AFE1_RXB_DSA2PD: Q11.1(B) R52.6
AFE1_RXB_PD2H: Q18.1(B) R197.5
AFE1_RXB_PD2L: Q19.1(B) R197.6
AFE1_RXBDSA1PD: R52.12 R53.5 R405.2
AFE1_RXBDSA2PD: R52.11 R53.6 R406.2
AFE1_RXBDSAFAST: R201.15 R202.2 U3.F11(RXBDSAFAST)
AFE1_RXBPD2H: R197.12 R198.5 R414.2
AFE1_RXBPD2L: R197.11 R198.6 R415.2
AFE1_RXC_DSA1PD: Q12.1(B) R52.7
AFE1_RXC_DSA2PD: Q13.1(B) R52.8
AFE1_RXC_PD2H: Q20.1(B) R197.7
AFE1_RXC_PD2L: Q21.1(B) R197.8
AFE1_RXCDSA1PD: R52.10 R53.7 R408.2
AFE1_RXCDSA2PD: R52.9 R53.8 R409.2
AFE1_RXCDSAFAST: R201.14 R202.3 U3.T14(RXCDSAFAST)
AFE1_RXCPD2H: R197.10 R198.7 R416.2
AFE1_RXCPD2L: R197.9 R198.8 R417.2
AFE1_RXD_DSA1PD: Q14.1(B) R197.1
AFE1_RXD_DSA2PD: Q15.1(B) R197.2
AFE1_RXD_PD2H: Q22.1(B) R199.1
AFE1_RXD_PD2L: Q23.1(B) R199.2
AFE1_RXDDSA1PD: R197.16 R198.1 R410.2
AFE1_RXDDSA2PD: R197.15 R198.2 R411.2
AFE1_RXDDSAFAST: R201.13 R202.4 U3.R11(RXDDSAFAST)
AFE1_RXDPD2H: R199.8 R200.1 R418.2
AFE1_RXDPD2L: R199.7 R200.2 R419.2
AFE1_RXDSASW: R203.9 R204.8 U3.D13(RXDSASW)
AFE1_RXFBNCO0: R201.12 R202.5 U3.C12(RXFBNCO0)
AFE1_RXFBNCO1: R201.11 R202.6 U3.G9(RXFBNCO1)
AFE1_RXFBNCO2: R201.10 R202.7 U3.V12(RXFBNCO2)
AFE1_RXFBNCO3: R201.9 R202.8 U3.P9(RXFBNCO3)
AFE1_RXFBSW1: R203.12 R204.5 U3.E11(RXFBSW1)
AFE1_RXFBSW2: R203.11 R204.6 U3.T11(RXFBSW2)
AFE1_RXTDD1: R203.14 R204.3 U3.D7(RXTDD1)
AFE1_RXTDD2: R203.13 R204.4 U3.U7(RXTDD2)
AFE1_SLEEPMODE: R205.12 R206.5 U3.P5(SLEEPMODE)
AFE1_TX1ENB: R205.14 R206.3 U3.D16(TXENB1)
AFE1_TX2ENB: R205.13 R206.4 U3.U16(TXENB2)
AFE1_TXDSASW: R203.10 R204.7 U3.U13(TXDSASW)
AFE1_TXTDD1: R203.16 R204.1 U3.C16(TXTDD1)
AFE1_TXTDD2: R203.15 R204.2 U3.V16(TXTDD2)
DACOUT: R422.2 ; port DACOUT
FMC_FBBANDSEL1: R206.16 ; port FMC_FBBANDSEL1
FMC_FBBANDSEL2: R206.15 ; port FMC_FBBANDSEL2
FMC_RXADSA1PD: R53.14 ; port FMC_RXADSA1PD
FMC_RXADSA2PD: R53.13 ; port FMC_RXADSA2PD
FMC_RXADSAFAST: R202.16 ; port FMC_RXADSAFAST
FMC_RXAPD2H: R198.14 ; port FMC_RXAPD2H
FMC_RXAPD2L: R198.13 ; port FMC_RXAPD2L
FMC_RXBDSA1PD: R53.12 ; port FMC_RXBDSA1PD
FMC_RXBDSA2PD: R53.11 ; port FMC_RXBDSA2PD
FMC_RXBDSAFAST: R202.15 ; port FMC_RXBDSAFAST
FMC_RXBPD2H: R198.12 ; port FMC_RXBPD2H
FMC_RXBPD2L: R198.11 ; port FMC_RXBPD2L
FMC_RXCDSA1PD: R53.10 ; port FMC_RXCDSA1PD
FMC_RXCDSA2PD: R53.9 ; port FMC_RXCDSA2PD
FMC_RXCDSAFAST: R202.14 ; port FMC_RXCDSAFAST
FMC_RXDDSA1PD: R198.16 ; port FMC_RXDDSA1PD
FMC_RXDDSA2PD: R198.15 ; port FMC_RXDDSA2PD
FMC_RXDDSAFAST: R202.13 ; port FMC_RXDDSAFAST
FMC_RXDSASW: R204.9 ; port FMC_RXDSASW
FMC_RXFBNCO0: R202.12 ; port FMC_RXFBNCO0
FMC_RXFBNCO1: R202.11 ; port FMC_RXFBNCO1
FMC_RXFBNCO2: R202.10 ; port FMC_RXFBNCO2
FMC_RXFBNCO3: R202.9 ; port FMC_RXFBNCO3
FMC_RXFBSW1: R204.12 ; port FMC_RXFBSW1
FMC_RXFBSW2: R204.11 ; port FMC_RXFBSW2
FMC_RXTDD1: R204.14 ; port FMC_RXTDD1
FMC_RXTDD2: R204.13 ; port FMC_RXTDD2
FMC_TXDSASW: R204.10 ; port FMC_TXDSASW
FMC_TXTDD1: R204.16 ; port FMC_TXTDD1
FMC_TXTDD2: R204.15 ; port FMC_TXTDD2
FTDI_DSASW_A: C612.2 J62.2 R203.7 R203.8 R425.2 ; port FTDI_DSASW_A
FTDI_FBBANDSEL_A: C614.2 J63.2 R205.1 R205.2 R426.2 ; port FTDI_FBBANDSEL_A
FTDI_RXDSAFAST_A: C615.2 J65.2 R201.1 R201.2 R201.3 R201.4 R428.2 ; port FTDI_RXDSAFAST_A
FTDI_RXFBNCO_A: C616.2 J66.2 R201.5 R201.6 R201.7 R201.8 R429.2 ; port FTDI_RXFBNCO_A
FTDI_RXFBSW_A: C611.2 J61.2 R203.5 R203.6 R424.2 ; port FTDI_RXFBSW_A
FTDI_RXTDD_MODE_A: C613.2 J60.2 R203.3 R203.4 R423.2 ; port FTDI_RXTDD_MODE_A
FTDI_TXTDD_MODE_A: C617.2 J67.2 R203.1 R203.2 R430.2 ; port FTDI_TXTDD_MODE_A
NetC610_1: C610.1 R402.1 S1.2 U3.C18(RESETB)
NetD12_2: D12.2(K) R407.2
NetD13_2: D13.2(K) R420.2
NetD14_2: D14.2(K) R427.2
NetQ4_3: Q4.3(C) R407.1
NetQ5_3: Q5.3(C) R420.1
NetQ6_3: Q6.3(C) Q7.3(C) Q8.3(C) Q9.3(C) Q10.3(C) Q11.3(C) Q12.3(C) Q13.3(C) Q14.3(C) Q15.3(C) Q16.3(C) Q17.3(C) Q18.3(C) Q19.3(C) Q20.3(C) Q21.3(C) Q22.3(C) Q23.3(C) R427.1
NetR205_9: R205.9 R206.8
NetR205_10: R205.10 R206.7
NetR205_11: R205.11 R206.6
NetR403_1: R403.1 U3.E8(RXADSA1PD)
NetR404_1: R404.1 U3.C9(RXADSA2PD)
NetR405_1: R405.1 U3.E12(RXBDSA1PD)
NetR406_1: R406.1 U3.D12(RXBDSA2PD)
NetR408_1: R408.1 U3.T8(RXCDSA1PD)
NetR409_1: R409.1 U3.V9(RXCDSA2PD)
NetR410_1: R410.1 U3.T12(RXDDSA1PD)
NetR411_1: R411.1 U3.U12(RXDDSA2PD)
NetR412_1: R412.1 U3.D8(RXAPD2H)
NetR413_1: R413.1 U3.D11(RXAPD2L)
NetR414_1: R414.1 U3.C7(RXBPD2H)
NetR415_1: R415.1 U3.E7(RXBPD2L)
NetR416_1: R416.1 U3.U8(RXCPD2H)
NetR417_1: R417.1 U3.U11(RXCPD2L)
NetR418_1: R418.1 U3.V7(RXDPD2H)
NetR419_1: R419.1 U3.T7(RXDPD2L)
NetR421_1: R421.1 U3.J5(SCANEN)
NetR422_1: R422.1 U3.G5(DACOUT)

Not connected (* = marked no-connect by the designer): R53 15* 16*; R198 9* 10*; R199 3* 4* 5* 6*; R200 3* 4* 5* 6* 7* 8*; R206 12* 13* 14*

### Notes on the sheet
- (near J59) SHORT 1-2,3-4

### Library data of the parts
C610-C617 = 0402ZC103KAT2A: CAP, CERM, 0.01 µF, 10 V,+/- 10%, X7R, 0402; Manufacturer: AVX; Polarized: N; CompType: Capacitor; Value: 0.01uF; U/M: EA; Cap_F: 0.00000001; Tolerance_%: 10; Value2: 10V; TaMin_C: -55; TaMax_C: 125; SizeArea_mm2: 0.5; SizeAreaWB_mm2: 3; SizeX_mm: 1; SizeZ_mm: 0.6; AEC Category: Q200
D12-D14 = LTST-C191TGKT: LED, Green, SMD; Manufacturer: Lite-On; Type: InGaN; Vf_V: 3.2; Value2: 3.2V; Io_A: 0.02; Value1: W; U/M: EA
J59 = 951204-8622-AR: Header, 2mm, 2x2, Gold, TH; Manufacturer: 3M; SymbolCreator: a0412235; Pitch_mm: 2; Gender: Male; Shrouded: N; Current_A: 1; Voltage_V: 1000; Cert_UL: Y
J60-J63 J65-J67 = TSW-102-07-T-S: Header, 2.54 mm, 2x1, Tin, TH; Manufacturer: Samtec; SymbolCreator: a0412235; Pitch_mm: 2.54; Gender: Male; Shrouded: N; Row_Count: 1; Current_A: 6.3; Voltage_V: 550; Cert_CSA: Y; Green_Lifecycle: Active; Green_REACh: Passed
Q4-Q23 = DTC114EET1G, ON Semiconductor: Transistor, NPN, 50 V, 0.1 A, AEC-Q101, SOT-416; CompType: BJT; PNP: 0; NPN: 1; Vceo_V: 50; Vcesat1_V: 0.25; Value: 50 V; IcRated_A: 0.1; Value1: 0.1 A; HfeMax: 60; TaMin_C: -55; TaMax_C: 150; SizeAreaWB_mm2: 6.76; SizeArea_mm2: 2.56; SizeX_mm: 1.6; SizeZ_mm: 0.95; U/M: EA; AEC Category: Q101; AEC Qualified: Y; Green_Lifecycle: Active; Green_REACh: Passed
R52 R53 R197 R198 R201-R206 = CMP-0015352-2: as R38 on sheet AFE1-PROGRAMMING INTERFACE
R199 R200 = CMP-0078922-1: RES ARRAY 4 RES ZERO OHM 0804; Manufacturer: Panasonic; Tolerance_%: 5%; Value_Code: 0; SizeArea_mm2: 2; AEC Qualified: Y; AEC Category: Q200; Res_ohm: 22; Value: 0; SizeZ_mm: 0.45; Green_REACh: Passed; EIA_Code: E24; TempCo: 200 ppm/C; AEC Grade: 1; Power_W: 62.5mW; VDC_V: 50V; Value2: 0.0625W; Green_Lifecycle: Active; CompType: Resistor
R402 R421 R423-R426 R428-R430 = CRCW04021K00JNED: as R36 on sheet AFE1-PROGRAMMING INTERFACE
R403-R406 R408-R419 = ERJ-2RKF49R9X: as R128 on sheet AFE1-RX-TX-INTERFACE
R407 R420 R427 = CRCW0402604RFKED: RES, 604, 1%, 0.063 W, 0402; Manufacturer: Vishay-Dale; CompType: Resistor; Value: 604; Value_Code: 604R; Tolerance_%: 1; Power_W: 0.063; Value2: 0.063W; VDC_V: 50; TempCo: 100 ppm/C; SizeArea_mm2: 0.5; SizeZ_mm: 0.6; EIA_Code: E96; U/M: EA; AEC Category: Q200
R422 = CRCW06030000Z0EA: RES, 0, 5%, 0.1 W, 0603; Manufacturer: Vishay-Dale; CompType: Resistor; Tolerance_%: 5; VDC_V: 75; Power_W: 0.1; Value: 0; U/M: EA; Value_Code: 0000; Value2: 0.1W; EIA_Code: E24; TempCo: 200 ppm/C; SizeArea_mm2: 1.28; SizeX_mm: 1.6; SizeY_mm: 0.8; SizeZ_mm: 1; AEC Category: Q200
S1 = 147873-2: Switch, SPST, Off-On, 50 mA,24V, SMD; Manufacturer: TE Connectivity; SymbolCreator: a0799628; SizeAreaWB_mm2: 48.4; SizeArea_mm2: 23.8; SizeX_mm: 6.8; SizeY_mm: 3.5; SizeZ_mm: 4.65; VDC_V: 24; PositionCount: 1; CurrentRating_mA: 50
U3 = CMP-0084351-1: as U3 on sheet AFE1-RX-TX-INTERFACE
